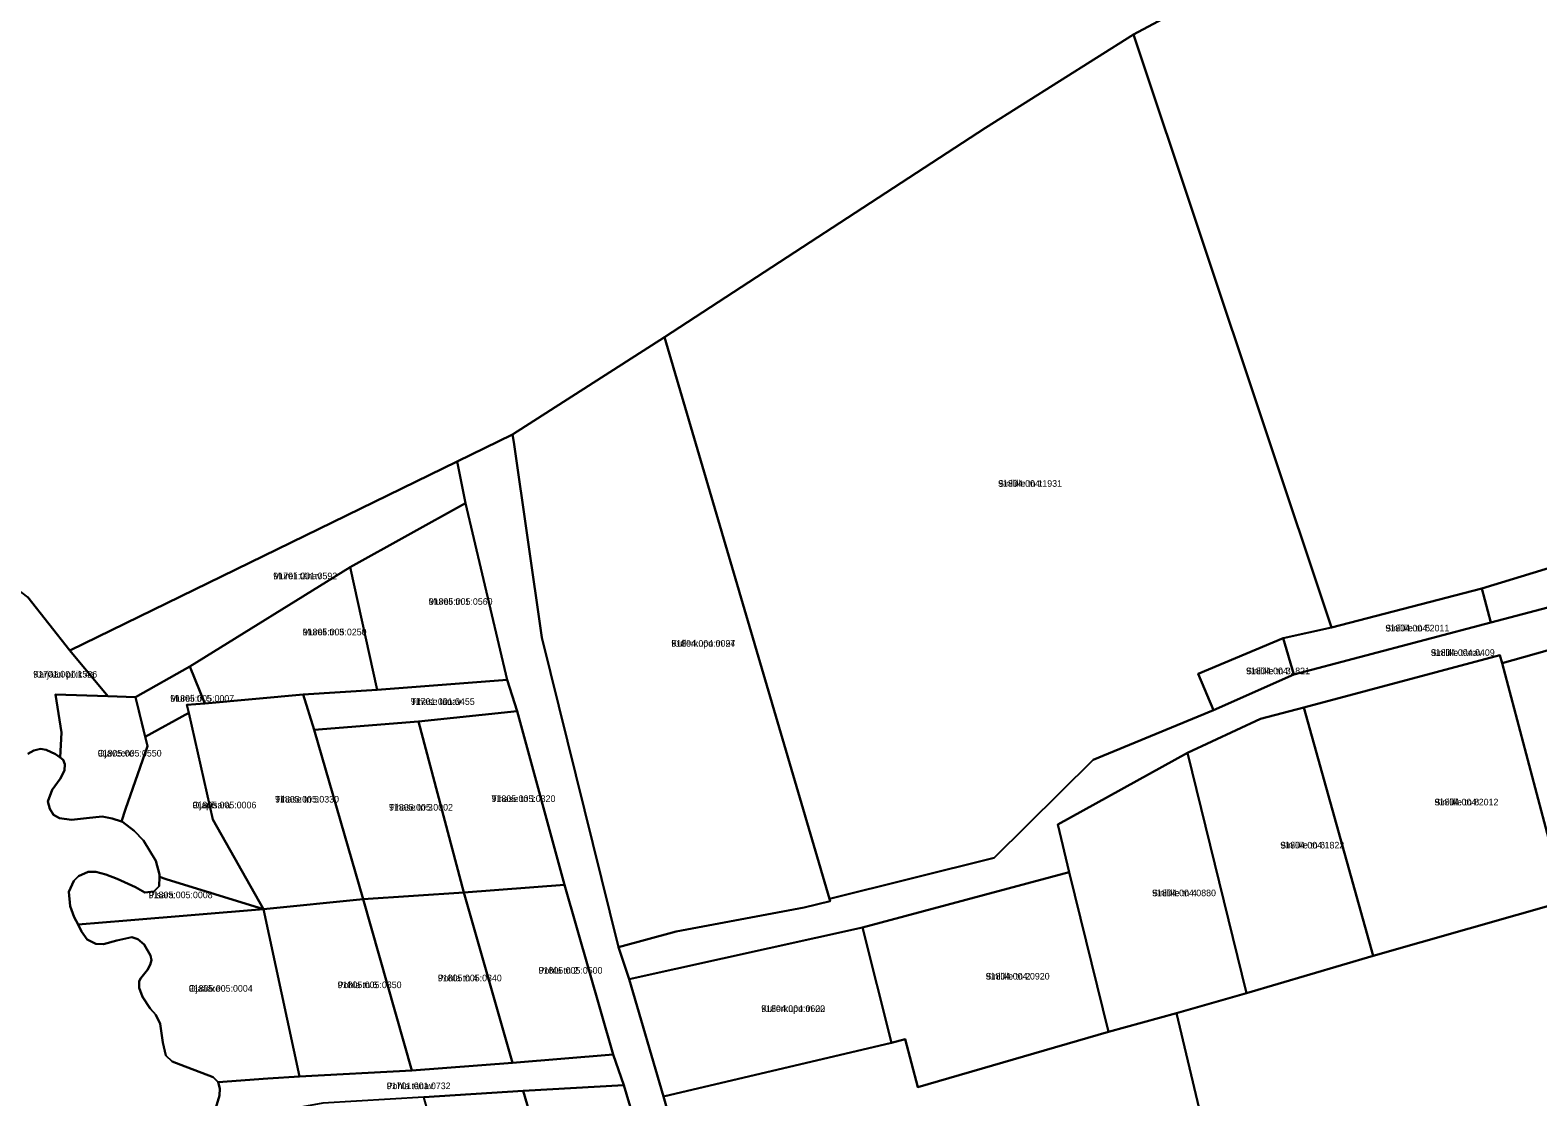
# Model space of a CAD drawing. Extents: x 655954 to 711923, y 6395079 to 6429745.
# Drawn here: x 680907.6 to 681249.8, y 6412285 to 6412527 of the extents above; entities that cross this region are included whole.
import ezdxf

# ---------------------------------------------------------------- set-up
doc = ezdxf.new("R2010")
doc.units = 0
for name, color, linetype in [('L_AADRESS', 7, 'Continuous'), ('PIIR', 7, 'Continuous'), ('TUNNUS', 7, 'Continuous')]:
    doc.layers.add(name, color=color, linetype=linetype)

msp = doc.modelspace()

# ---------------------------------------------------------------- linework, layer by layer
at = {"layer": 'PIIR'}
for points in [[(681631.25, 6412784.39), (681524.04, 6412713.27), (681400.11, 6412655.35), (681158.01, 6412526.04), (681124.39, 6412504.87), (681051.56, 6412457.34), (681017.07, 6412435.31), (681004.5, 6412429.19), (680916.58, 6412386.27), (680907.04, 6412398.35), (680881.9, 6412417.62), (680832.81, 6412523.6), (680811.9, 6412594.2), (680849.16, 6412621.46), (680903.12, 6412670.17), (681120.91, 6412675.42), (681109.41, 6412705.01), (680986.04, 6412708.3), (680879.12, 6412719.8), (680806.44, 6412709.75), (680770.1, 6412691.18), (680731.48, 6412687.34), (680659.4, 6412646.08)], [(681053.74, 6412249.18), (681042.3, 6412287.68), (681039.94, 6412294.61), (681028.88, 6412333.14), (681018.1, 6412372.56), (681015.85, 6412379.63), (681006.4, 6412419.71), (681004.5, 6412429.19), (681017.07, 6412435.31), (681017.33, 6412433.51), (681023.75, 6412389.2), (681041.11, 6412318.99), (681043.53, 6412311.72), (681051.29, 6412285.13), (681058.75, 6412259.04)], [(681284.36, 6412395.4), (681241.64, 6412383.4), (681241.16, 6412385.23), (681196.67, 6412373.39), (681186.84, 6412370.76), (681170.28, 6412363.06), (681140.78, 6412346.81), (681143.42, 6412336.04), (681096.5, 6412323.49), (681043.53, 6412311.72), (681041.11, 6412318.99), (681054.23, 6412322.55), (681083.23, 6412328), (681089.16, 6412329.45), (681089.02, 6412329.92), (681126.35, 6412339.28), (681148.82, 6412361.49), (681176.15, 6412372.75), (681194.39, 6412380.85), (681239.1, 6412392.64), (681281.89, 6412403.91)], [(680907.04, 6412398.35), (680916.58, 6412386.27), (680925.2, 6412375.91), (680913.38, 6412376.3), (680914.69, 6412367.65), (680914.44, 6412361.98), (680913.31, 6412362.79), (680911.2, 6412363.74), (680909.98, 6412363.95), (680908.44, 6412363.63), (680907.07, 6412362.84)], [(680907.07, 6412362.84), (680908.44, 6412363.63), (680909.98, 6412363.95), (680911.2, 6412363.74), (680913.31, 6412362.79), (680914.44, 6412361.98), (680915.11, 6412361.47), (680915.48, 6412360.51), (680915.38, 6412359.03), (680914.44, 6412357.18), (680912.56, 6412354.69), (680911.61, 6412352), (680912.05, 6412350.4), (680912.93, 6412349.01), (680914.28, 6412348.23), (680916.94, 6412347.88), (680920.4, 6412348.24), (680923.94, 6412348.61), (680926.2, 6412348.21), (680928.29, 6412347.49), (680928.55, 6412347.39), (680931.21, 6412345.37), (680933.32, 6412343.16), (680936.1, 6412338.6), (680936.94, 6412335.48), (680936.92, 6412334.93), (680936.86, 6412332.84), (680935.7, 6412331.62), (680933.63, 6412331.41), (680931.5, 6412332.63), (680927.35, 6412334.51), (680924.74, 6412335.48), (680922.52, 6412336.07), (680920.77, 6412336.07), (680918.55, 6412335.11), (680917.49, 6412334.05), (680916.4, 6412331.51), (680916.65, 6412328.29), (680917.6, 6412325.8), (680918.48, 6412324.12), (680919.24, 6412322.52), (680920.51, 6412320.72), (680922.52, 6412319.77), (680924.27, 6412319.66), (680927.23, 6412320.51), (680930.67, 6412321.25), (680932.05, 6412320.83), (680933.47, 6412319.61), (680934.9, 6412317.12), (680935.11, 6412316.01), (680934.85, 6412314.95), (680934.21, 6412313.84), (680932.73, 6412311.99), (680932.37, 6412311.29), (680932.34, 6412309.74), (680933.09, 6412307.76), (680934.81, 6412305.09), (680936.12, 6412303.68), (680937.13, 6412301.59), (680937.71, 6412297.34), (680938.42, 6412294.41), (680939.85, 6412293.06), (680941.76, 6412292.3), (680949.14, 6412289.53), (680950.29, 6412288.38), (680950.61, 6412286.95), (680950.53, 6412285.32), (680948.65, 6412278.97)]]:
    msp.add_lwpolyline(points, dxfattribs=at)
for points in [[(681400.11, 6412655.35), (681431.81, 6412475.51), (681418.14, 6412467.86), (681365.67, 6412438.51), (681336.67, 6412430.86), (681307.73, 6412422), (681279.16, 6412413.24), (681237.04, 6412400.37), (681202.95, 6412391.5), (681158.01, 6412526.04)], [(681124.39, 6412504.87), (681158.01, 6412526.04), (681202.95, 6412391.5), (681191.93, 6412389.08), (681172.65, 6412381.03), (681176.15, 6412372.75), (681148.82, 6412361.49), (681126.35, 6412339.28), (681089.02, 6412329.92), (681051.56, 6412457.34)], [(681017.07, 6412435.31), (681051.56, 6412457.34), (681089.02, 6412329.92), (681089.16, 6412329.45), (681083.23, 6412328), (681054.23, 6412322.55), (681041.11, 6412318.99), (681023.75, 6412389.2), (681017.33, 6412433.51)], [(680980.21, 6412405.16), (680943.8, 6412382.62), (680931.47, 6412375.7), (680925.2, 6412375.91), (680916.58, 6412386.27), (681004.5, 6412429.19), (681006.4, 6412419.71)], [(680986.34, 6412377.34), (680980.21, 6412405.16), (681006.4, 6412419.71), (681015.85, 6412379.63)], [(681239.1, 6412392.64), (681237.04, 6412400.37), (681279.16, 6412413.24), (681281.89, 6412403.91)], [(680986.34, 6412377.34), (680969.57, 6412376.33), (680947.2, 6412374.29), (680943.8, 6412382.62), (680980.21, 6412405.16)], [(681237.04, 6412400.37), (681239.1, 6412392.64), (681194.39, 6412380.85), (681191.93, 6412389.08), (681202.95, 6412391.5)], [(681284.36, 6412395.4), (681299.92, 6412342.01), (681255.92, 6412329.46), (681241.64, 6412383.4)], [(681191.93, 6412389.08), (681194.39, 6412380.85), (681176.15, 6412372.75), (681172.65, 6412381.03)], [(681241.16, 6412385.23), (681241.64, 6412383.4), (681255.92, 6412329.46), (681212.34, 6412317.04), (681196.67, 6412373.39)], [(680931.47, 6412375.7), (680943.8, 6412382.62), (680947.2, 6412374.29), (680943.17, 6412373.98), (680943.58, 6412372.15), (680933.72, 6412366.71)], [(681018.1, 6412372.56), (680995.72, 6412370.2), (680972.04, 6412368.29), (680969.57, 6412376.33), (680986.34, 6412377.34), (681015.85, 6412379.63)], [(680914.69, 6412367.65), (680913.38, 6412376.3), (680925.2, 6412375.91), (680931.47, 6412375.7), (680934.26, 6412364.55), (680929.26, 6412350.26), (680928.29, 6412347.49), (680926.2, 6412348.21), (680923.94, 6412348.61), (680920.4, 6412348.24), (680916.94, 6412347.88), (680914.28, 6412348.23), (680912.93, 6412349.01), (680912.05, 6412350.4), (680911.61, 6412352), (680912.56, 6412354.69), (680914.44, 6412357.18), (680915.38, 6412359.03), (680915.48, 6412360.51), (680915.11, 6412361.47), (680914.44, 6412361.98)], [(680983.19, 6412329.88), (680960.57, 6412327.58), (680949.02, 6412347.94), (680943.58, 6412372.15), (680943.17, 6412373.98), (680947.2, 6412374.29), (680969.57, 6412376.33), (680972.04, 6412368.29)], [(680933.72, 6412366.71), (680943.58, 6412372.15), (680949.02, 6412347.94), (680960.57, 6412327.58), (680938.49, 6412334.45), (680936.92, 6412334.93), (680936.94, 6412335.48), (680936.1, 6412338.6), (680933.32, 6412343.16), (680931.21, 6412345.37), (680928.55, 6412347.39), (680928.29, 6412347.49), (680929.26, 6412350.26), (680934.26, 6412364.55)], [(680995.72, 6412370.2), (681018.1, 6412372.56), (681028.88, 6412333.14), (681006.03, 6412331.43)], [(681196.67, 6412373.39), (681212.34, 6412317.04), (681183.61, 6412308.53), (681170.28, 6412363.06), (681186.84, 6412370.76)], [(680995.72, 6412370.2), (681006.03, 6412331.43), (680983.19, 6412329.88), (680972.04, 6412368.29)], [(681152.34, 6412299.81), (681143.42, 6412336.04), (681140.78, 6412346.81), (681170.28, 6412363.06), (681183.61, 6412308.53), (681167.77, 6412304.01)], [(681328.62, 6412350.34), (681350.64, 6412272.52), (681360.54, 6412232.94), (681368.44, 6412234.18), (681393.19, 6412133.84), (681385.56, 6412131.89), (681365.57, 6412212.54), (681268.71, 6412187.17), (681303.76, 6412042.93), (681275.58, 6412043.52), (681270.46, 6412062.78), (681228.97, 6412217.72), (681190.9, 6412207.5), (681184.65, 6412233.77), (681178.3, 6412260), (681172.89, 6412282.37), (681167.77, 6412304.01), (681183.61, 6412308.53), (681212.34, 6412317.04), (681255.92, 6412329.46), (681298.51, 6412341.6)], [(680933.63, 6412331.41), (680935.7, 6412331.62), (680936.86, 6412332.84), (680936.92, 6412334.93), (680938.49, 6412334.45), (680960.57, 6412327.58), (680929.55, 6412325.01), (680918.48, 6412324.12), (680917.6, 6412325.8), (680916.65, 6412328.29), (680916.4, 6412331.51), (680917.49, 6412334.05), (680918.55, 6412335.11), (680920.77, 6412336.07), (680922.52, 6412336.07), (680924.74, 6412335.48), (680927.35, 6412334.51), (680931.5, 6412332.63)], [(681017.05, 6412292.76), (681006.03, 6412331.43), (681028.88, 6412333.14), (681039.94, 6412294.61)], [(681103.06, 6412297.32), (681096.5, 6412323.49), (681143.42, 6412336.04), (681152.34, 6412299.81), (681109.04, 6412287.26), (681106.19, 6412298.14)], [(680994.18, 6412291.02), (680968.7, 6412289.64), (680960.57, 6412327.58), (680983.19, 6412329.88)], [(681017.05, 6412292.76), (680994.18, 6412291.02), (680983.19, 6412329.88), (681006.03, 6412331.43)], [(680918.48, 6412324.12), (680929.55, 6412325.01), (680960.57, 6412327.58), (680968.7, 6412289.64), (680961.57, 6412289.23), (680950.29, 6412288.38), (680949.14, 6412289.53), (680941.76, 6412292.3), (680939.85, 6412293.06), (680938.42, 6412294.41), (680937.71, 6412297.34), (680937.13, 6412301.59), (680936.12, 6412303.68), (680934.81, 6412305.09), (680933.09, 6412307.76), (680932.34, 6412309.74), (680932.37, 6412311.29), (680932.73, 6412311.99), (680934.21, 6412313.84), (680934.85, 6412314.95), (680935.11, 6412316.01), (680934.9, 6412317.12), (680933.47, 6412319.61), (680932.05, 6412320.83), (680930.67, 6412321.25), (680927.23, 6412320.51), (680924.27, 6412319.66), (680922.52, 6412319.77), (680920.51, 6412320.72), (680919.24, 6412322.52)], [(681051.29, 6412285.13), (681043.53, 6412311.72), (681096.5, 6412323.49), (681103.06, 6412297.32)], [(681058.75, 6412259.04), (681051.29, 6412285.13), (681103.06, 6412297.32), (681106.19, 6412298.14), (681109.04, 6412287.26), (681152.34, 6412299.81), (681167.77, 6412304.01), (681172.89, 6412282.37), (681122.23, 6412269.96), (681114.62, 6412272.26)], [(681039.94, 6412294.61), (681042.3, 6412287.68), (681019.45, 6412286.4), (680996.96, 6412284.96), (680974, 6412283.59), (680948.65, 6412278.97), (680950.53, 6412285.32), (680950.61, 6412286.95), (680950.29, 6412288.38), (680961.57, 6412289.23), (680968.7, 6412289.64), (680994.18, 6412291.02), (681017.05, 6412292.76)], [(681030.76, 6412247.91), (681007.81, 6412246.45), (680996.96, 6412284.96), (681019.45, 6412286.4)], [(681019.45, 6412286.4), (681042.3, 6412287.68), (681053.74, 6412249.18), (681030.76, 6412247.91)]]:
    msp.add_lwpolyline(points, close=True, dxfattribs=at)

# ---------------------------------------------------------------- texts
at = {"layer": 'L_AADRESS'}
for s, p in [('Sinilille tn 1', (681127.26, 6412423.42)), ('Mureli tänav', (680962.77, 6412402.45)), ('Mureli tn 1', (680998.03, 6412396.65)), ('Mureli tn 3', (680969.44, 6412389.73)), ('Sinilille tn 5', (681215.15, 6412390.61)), ('Kullerkupu tn 24', (681053.11, 6412387.15)), ('Sinilille tänav', (681225.46, 6412385.07)), ('Karjääri põik 4a', (680908.3, 6412380.15)), ('Sinilille tn 3', (681183.53, 6412380.91)), ('Mureli tn 5', (680939.39, 6412374.67)), ('Tihase tänav', (680993.98, 6412373.96)), ('Ojaveere', (680922.93, 6412362.24)), ('Tihase tn 5', (680963.18, 6412351.8)), ('Tihase tn 1', (681012.3, 6412351.92)), ('Ojapisara', (680944.43, 6412350.48)), ('Tihase tn 3', (680989.04, 6412349.97)), ('Sinilille tn 8', (681226.3, 6412351.15)), ('Sinilille tn 6', (681191.31, 6412341.38)), ('Pisara', (680934.5, 6412330.1)), ('Sinilille tn 4', (681162.2, 6412330.55)), ('Pohla tn 4', (681000.12, 6412311.25)), ('Pohla tn 2', (681022.98, 6412312.97)), ('Sinilille tn 2', (681124.45, 6412311.65)), ('Ojaääre', (680943.59, 6412308.89)), ('Pohla tn 6', (680977.38, 6412309.7)), ('Kullerkupu tn 22', (681073.5, 6412304.31)), ('Pohla tänav', (680988.51, 6412286.79))]:
    msp.add_text(s, height=1.5, dxfattribs=at).set_placement(p)
at = {"layer": 'TUNNUS'}
for s, p in [('91804:004:1931', (681127.26, 6412423.42)), ('91701:001:0592', (680962.77, 6412402.45)), ('91805:005:0560', (680998.03, 6412396.65)), ('91805:005:0250', (680969.44, 6412389.73)), ('91804:004:2011', (681215.15, 6412390.61)), ('91804:004:0097', (681053.11, 6412387.15)), ('91804:004:0409', (681225.46, 6412385.07)), ('91701:001:1526', (680908.3, 6412380.15)), ('91804:004:1821', (681183.53, 6412380.91)), ('91805:005:0007', (680939.39, 6412374.67)), ('91701:001:0455', (680993.98, 6412373.96)), ('91805:005:0550', (680922.93, 6412362.24)), ('91805:005:0330', (680963.18, 6412351.8)), ('91805:005:0320', (681012.3, 6412351.92)), ('91805:005:0006', (680944.43, 6412350.48)), ('91805:005:0002', (680989.04, 6412349.97)), ('91804:004:2012', (681226.3, 6412351.15)), ('91804:004:1822', (681191.31, 6412341.38)), ('91805:005:0008', (680934.5, 6412330.1)), ('91804:004:0880', (681162.2, 6412330.55)), ('91805:005:0340', (681000.12, 6412311.25)), ('91805:005:0500', (681022.98, 6412312.97)), ('91804:004:0920', (681124.45, 6412311.65)), ('91805:005:0004', (680943.59, 6412308.89)), ('91805:005:0350', (680977.38, 6412309.7)), ('91804:004:0600', (681073.5, 6412304.31)), ('91701:001:0732', (680988.51, 6412286.79))]:
    msp.add_text(s, height=1.5, dxfattribs=at).set_placement(p)

doc.saveas('drawing.dxf')
